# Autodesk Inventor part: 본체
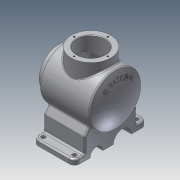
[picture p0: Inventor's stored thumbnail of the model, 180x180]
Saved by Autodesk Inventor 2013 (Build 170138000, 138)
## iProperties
Created: 2018-08
Part Number: 본체
Material: 알루미늄 6061
Document SubType Name: Modeling
Designer: Administrator
Density: 2.71 g/cm^3
Mass: 1885.91 g
Surface Area: 1085.67 cm^2
Volume: 695.909 cm^3
Author: Administrator
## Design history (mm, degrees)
sketch "스케치1"
  geometry: L1 (40, 70)-(-40, 70); L2 (-40, 70)-(-40, -70); L3 (-40, -70)-(40, -70); L4 (40, -70)-(40, 70); L5 (40, 70)-(-40, -70); L6 (-40, 70)-(40, -70); 1 further point
  constraints: 12 end point, 2 midpoint, 2 parallel, 1 horizontal, 1 perpendicular
  dimensions: "d0" = 80 distance of L3.end L2.end; "d1" = 140 distance of L2.end L1.end
extrude "돌출1" new body sketch "스케치1" distance "d2" = 10; taper "d3" = 0 deg
sketch "스케치2"
  geometry: L1 (0, 0)-(0, 82); L2 (48.671, 132)-(-48, 132); L3 (-48, 132)-(-48, 120); L4 (-48, 120)-(-60, 120); L5 (-60, 120)-(-60, 82); L6 (-60, 82)-(60, 82); L7 (-40, 0)-(-40, 10) reference; A1 r 116 centre (-56, 82) between (60, 82) and (48.671, 132)
  constraints: 12 end point, 2 point on circle, 1 centre point, 1 midpoint, 1 parallel, 1 perpendicular, 1 point on line, 1 vertical
  dimensions: "d4" = 82 distance of L1.start L1.end; "d5" = 120 distance of L6.end L5.end; "d6" = 116 radius of A1; "d9" = 12 distance between parallel lines of L3 L5; "d12" = 108 horizontal distance of L2.end L6.end; "d83" = 100 diameter of L2 L6; "d84" = 76 diameter of L4 L6; "d85" = 48 distance from line of L1.end L3
revolve "회전1" sketch "스케치2" stored, may be unused: angle "d13" = 90 deg
sketch "스케치3"
  geometry: L1 (-60, 44)-(-60, 120) reference; L2 (-60, 82)-(60, 82); L3 (42.163, 122)-(-38, 122); L4 (-38, 122)-(-38, 109); L5 (-38, 109)-(-60, 109); A1 r 116 centre (-56, 82) between (48.671, 32) and (48.671, 132) reference; A2 r 106 centre (-56, 82) between (50, 82) and (42.163, 122); 1 further point
  constraints: 8 end point, 3 point on circle, 2 parallel, 2 point on line, 1 centre point, 1 midpoint, 1 perpendicular
  dimensions: "d14" = 10 radial gap between concentric circles of A2 A1; "d15" = 80 diameter of L3 L2; "d16" = 22 distance between parallel lines of L1 L4; "d17" = 54 diameter of L5 L2
revolve "회전2" sketch "스케치3" stored, may be unused: angle "d18" = 90 deg
fillet "모깎기1" dims "d19" = 10
sketch "스케치4"
  geometry: A1 r 10 centre (30, 60) between (40, 60) and (30, 70) reference; A2 r 10 centre (-30, 60) between (-30, 70) and (-40, 60) reference; A3 r 10 centre (-30, -60) between (-40, -60) and (-30, -70) reference; A4 r 10 centre (30, -60) between (30, -70) and (40, -60) reference; 5 further points
  constraints: 4 coincident
hole "구멍1" sketch "스케치4" at (-30, 60), (-30, -60), (30, -60), (30, 60) diameter "d20" = 8; stored, may be unused: countersink angle "d24" = 90 deg, drill point angle "d26" = 118 deg; dims "d21" = 6, "d22" = 4, "d23" = 2, "d25" = 8
sketch "스케치5"
  geometry: L1 (10, 70)-(10, -70) reference; L2 (10, -70)-(0, -70) reference; L3 (0, -70)-(0, 70) reference; L4 (0, 70)-(10, 70) reference; L5 (10, 70)-(52.41, 40.304); L6 (10, 50)-(38.563, 50); L7 (52.41, 40.304)-(38.563, 50); L8 (10, -70)-(52.41, -40.304); L9 (10, -50)-(38.563, -50); L10 (52.41, -40.304)-(38.563, -50); C1 r 40 at (82, 0) reference; A1 r 50 centre (82, 0) between (52.41, 40.304) and (52.41, -40.304) reference; 1 further point
  constraints: 12 end point, 4 point on line, 2 collinear, 2 parallel, 2 point on circle
  dimensions: "d29" = 35 deg angle of L4 L5; "d30" = 20 distance between parallel lines of L6 L4; "d31" = 35 deg angle of L2 L8; "d32" = 20 distance between parallel lines of L2 L9
extrude "돌출2" join sketch "스케치5" stored distance "d33" = 80; taper "d34" = 0 deg
sketch "스케치6"
  geometry: L1 (0, 0)-(120, 0) reference; C1 r 17.5 at (37.5, 0); C2 r 12.5 at (87.5, 0); 1 further point
  constraints: 2 centre point, 2 point on line
  dimensions: "d35" = 35 diameter of C1; "d36" = 25 diameter of C2; "d37" = 22.5 distance of point (60, 0) C1.centre; "d38" = 27.5 distance of C2.centre point (60, 0)
extrude "돌출3" cut sketch "스케치6" stored distance "d39" = 80; taper "d40" = 0 deg
node "작업 평면1"
sketch "스케치7"
  geometry: L1 (48, 50)-(48, -50) reference; L2 (40, -50)-(-40, -50) reference; C1 r 38 at (-2, 0); 1 further point
  constraints: 1 centre point, 1 coincident
  dimensions: "d42" = 76 diameter of C1; "d86" = 50 distance from line of point (-2, 0) L1; "d87" = 50 distance from line of L2 point (-2, 0)
extrude "돌출4" join sketch "스케치7" stored distance "d43" = 80; taper "d44" = 0 deg
sketch "스케치8"
  geometry: C1 r 38 at (0, 0) reference; C2 r 27 at (0, 0)
  constraints: 1 centre point, 1 coincident
  dimensions: "d45" = 54 diameter of C2
extrude "돌출5" cut sketch "스케치8" stored distance "d46" = 80; taper "d47" = 0 deg
sketch "스케치9"
  geometry: L1 (0, 0)-(0, 32.5); C1 r 38 at (0, 0) reference; 1 further point
  constraints: 2 end point, 1 coincident, 1 vertical
  dimensions: "d48" = 32.5 distance of L1.start L1.end
hole "구멍2" sketch "스케치9" at (0, 32.5) diameter "d49" = 3.242; stored, may be unused: countersink angle "d53" = 90 deg, drill point angle "d55" = 118 deg; dims "d50" = 8, "d51" = 4, "d52" = 2, "d54" = 10
sketch "스케치10"
  geometry: L1 (0, 0)-(0, 32.5); C1 r 38 at (0, 0) reference; 2 further points
  constraints: 2 end point, 1 coincident, 1 vertical
  dimensions: "d59" = 32.5 distance of L1.start L1.end
hole "구멍3" sketch "스케치10" at (0, 32.5) diameter "d60" = 3.242; stored, may be unused: countersink angle "d64" = 90 deg, drill point angle "d66" = 118 deg; dims "d61" = 8, "d62" = 4, "d63" = 2, "d65" = 10
chamfer "모따기1" distance "d70" = 1; stored, may be unused: second distance "d71" = 2, angle "d72" = 45 deg
fillet "모깎기2" dims "d73" = 3
fillet "모깎기3" dims "d74" = 3
fillet "모깎기4" dims "d75" = 3
fillet "모깎기5" dims "d76" = 3
fillet "모깎기6" dims "d77" = 3
node "작업 평면3"
sketch "스케치15"
  geometry: C1 r 50 at (82, 0) reference; C2 r 32.5 at (82, 0); 1 further point
  constraints: 1 centre point, 1 coincident, 1 other
  dimensions: "d89" = 65 diameter of C2
feature "엠보싱1" sketch "스케치15" dims "d0" = 80, "d1" = 140, "d90" = 0.5, "d91" = 0
node "솔리드1"
pattern_circular "원형 패턴1" dims angle "d57" = 360 deg
pattern_circular "원형 패턴2" dims angle "d68" = 360 deg
node "절단 모서리 투영1"
other parameters: "d41" = 147
